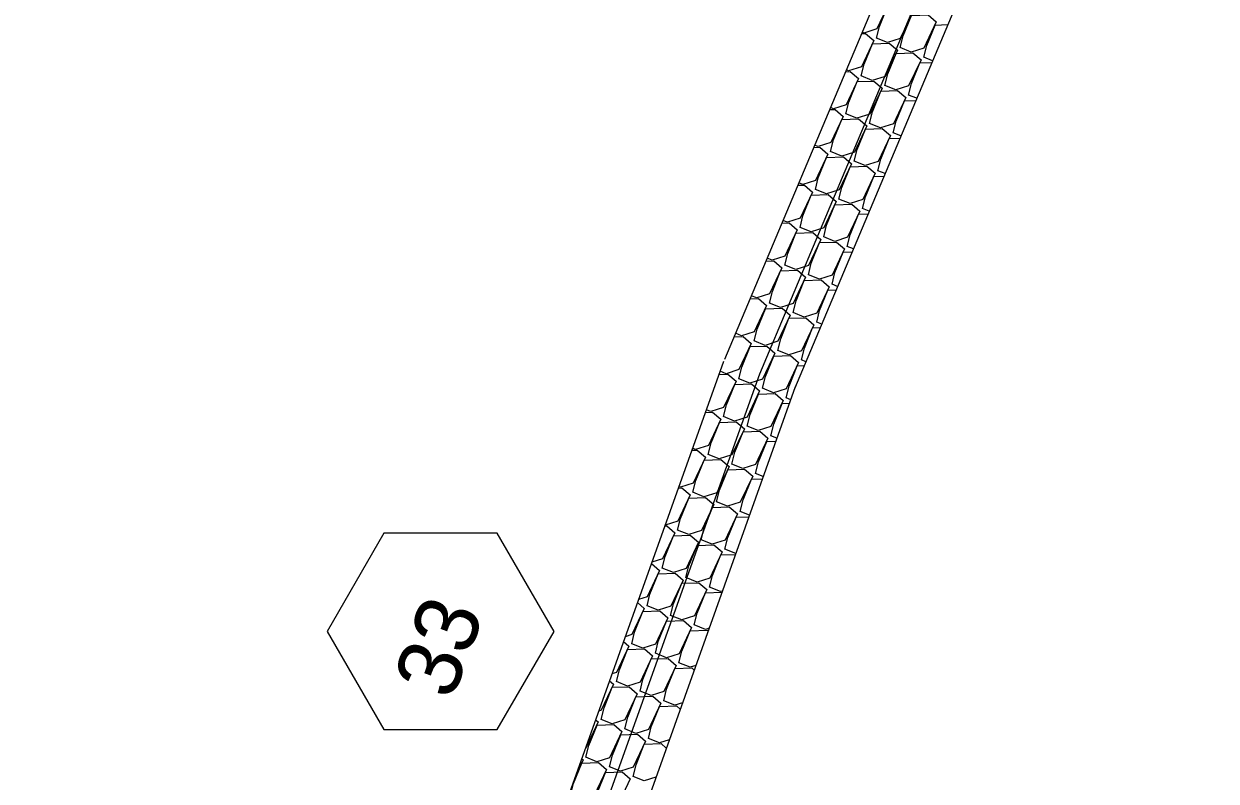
# Model space of a CAD drawing. Extents: x 2384780 to 2405432, y 547869 to 573706.
# Drawn here: x 2395434.7 to 2395528.6, y 556711.6 to 556771.3 of the extents above; entities that cross this region are included whole.
import ezdxf

# ---------------------------------------------------------------- set-up
doc = ezdxf.new("R2010")
doc.units = 0
for name, color, linetype in [('Old_Level_18', 7, 'Continuous'), ('Old_Level_20', 7, 'Continuous'), ('Prop Drainage Box Number Symbol CELL', 7, 'Continuous')]:
    doc.layers.add(name, color=color, linetype=linetype)

msp = doc.modelspace()

# ---------------------------------------------------------------- linework, layer by layer
at = {"layer": 'Old_Level_18'}
for p, q in [((2395525.876, 556822.715), (2395492.638, 556743.689)), ((2395492.638, 556743.689), (2395437.477, 556589.14))]:
    msp.add_line(p, q, dxfattribs=at)
at = {"layer": 'Old_Level_20'}
for p, q in [((2395523.11, 556823.878), (2395489.873, 556744.852)), ((2395528.644, 556821.559), (2395495.404, 556742.526)), ((2395489.813, 556744.697), (2395434.652, 556590.148)), ((2395495.464, 556742.68), (2395440.303, 556588.131))]:
    msp.add_line(p, q, dxfattribs=at)
for points in [[(2395501.933, 556773.519), (2395502.216, 556773.529), (2395502.856, 556772.979), (2395501.882, 556770.914), (2395500.88, 556770.596), (2395500.729, 556770.657)], [(2395501.872, 556770.195), (2395502.103, 556771.115), (2395502.755, 556772.729), (2395504.079, 556772.776), (2395504.72, 556772.226), (2395503.745, 556770.161), (2395502.743, 556769.843), (2395501.872, 556770.195)], [(2395503.735, 556769.442), (2395503.967, 556770.363), (2395504.619, 556771.976), (2395505.943, 556772.023), (2395506.584, 556771.473), (2395505.609, 556769.408), (2395504.607, 556769.09), (2395503.735, 556769.442)], [(2395505.599, 556768.689), (2395505.831, 556769.61), (2395506.482, 556771.223), (2395507.485, 556771.259)], [(2395500.677, 556770.532), (2395501.01, 556770.544), (2395501.65, 556769.993), (2395500.675, 556767.928), (2395499.674, 556767.611), (2395499.481, 556767.688)], [(2395500.666, 556767.209), (2395500.897, 556768.13), (2395501.549, 556769.743), (2395502.873, 556769.791), (2395503.514, 556769.24), (2395502.539, 556767.175), (2395501.537, 556766.858), (2395500.666, 556767.209)], [(2395502.529, 556766.456), (2395502.761, 556767.377), (2395503.413, 556768.99), (2395504.737, 556769.037), (2395505.377, 556768.488), (2395504.403, 556766.422), (2395503.401, 556766.105), (2395502.529, 556766.456)], [(2395506.288, 556768.411), (2395505.599, 556768.689)], [(2395499.421, 556767.544), (2395499.803, 556767.558), (2395500.444, 556767.008), (2395499.469, 556764.943), (2395498.467, 556764.625), (2395498.233, 556764.72)], [(2395504.393, 556765.704), (2395504.624, 556766.624), (2395505.276, 556768.237), (2395506.229, 556768.271)], [(2395499.459, 556764.224), (2395499.691, 556765.144), (2395500.343, 556766.758), (2395501.667, 556766.805), (2395502.308, 556766.255), (2395501.333, 556764.19), (2395500.331, 556763.872), (2395499.459, 556764.224)], [(2395501.323, 556763.471), (2395501.555, 556764.391), (2395502.206, 556766.005), (2395503.53, 556766.052), (2395504.171, 556765.502), (2395503.197, 556763.437), (2395502.195, 556763.119), (2395501.323, 556763.471)], [(2395505.039, 556765.443), (2395504.393, 556765.704)], [(2395503.186, 556762.718), (2395503.418, 556763.639), (2395504.07, 556765.252), (2395504.972, 556765.284)], [(2395498.164, 556764.557), (2395498.597, 556764.573), (2395499.238, 556764.022), (2395498.263, 556761.957), (2395497.261, 556761.639), (2395496.985, 556761.751)], [(2395498.253, 556761.238), (2395498.485, 556762.159), (2395499.137, 556763.772), (2395500.461, 556763.819), (2395501.101, 556763.27), (2395500.127, 556761.204), (2395499.124, 556760.887), (2395498.253, 556761.238)], [(2395500.117, 556760.486), (2395500.348, 556761.406), (2395501, 556763.019), (2395502.324, 556763.066), (2395502.965, 556762.517), (2395501.99, 556760.451), (2395500.988, 556760.133), (2395500.117, 556760.486)], [(2395503.79, 556762.474), (2395503.186, 556762.718)], [(2395501.98, 556759.733), (2395502.212, 556760.653), (2395502.864, 556762.266), (2395503.715, 556762.297)], [(2395496.908, 556761.57), (2395497.391, 556761.587), (2395498.031, 556761.037), (2395497.057, 556758.971), (2395496.055, 556758.654), (2395495.736, 556758.782)], [(2395497.047, 556758.253), (2395497.279, 556759.173), (2395497.93, 556760.787), (2395499.255, 556760.834), (2395499.895, 556760.284), (2395498.92, 556758.219), (2395497.918, 556757.901), (2395497.047, 556758.253)], [(2395498.911, 556757.5), (2395499.142, 556758.42), (2395499.794, 556760.034), (2395501.118, 556760.081), (2395501.759, 556759.531), (2395500.784, 556757.466), (2395499.782, 556757.148), (2395498.911, 556757.5)], [(2395500.774, 556756.747), (2395501.006, 556757.667), (2395501.658, 556759.28), (2395502.459, 556759.309)], [(2395502.541, 556759.506), (2395501.98, 556759.733)], [(2395495.652, 556758.582), (2395496.184, 556758.601), (2395496.825, 556758.051), (2395495.851, 556755.986), (2395494.848, 556755.668), (2395494.488, 556755.814)], [(2395495.84, 556755.267), (2395496.072, 556756.188), (2395496.724, 556757.801), (2395498.048, 556757.848), (2395498.689, 556757.299), (2395497.714, 556755.233), (2395496.712, 556754.915), (2395495.84, 556755.267)], [(2395497.704, 556754.515), (2395497.936, 556755.435), (2395498.588, 556757.048), (2395499.912, 556757.096), (2395500.553, 556756.546), (2395499.578, 556754.48), (2395498.576, 556754.162), (2395497.704, 556754.515)], [(2395499.568, 556753.762), (2395499.8, 556754.682), (2395500.451, 556756.295), (2395501.202, 556756.322)], [(2395501.293, 556756.537), (2395500.774, 556756.747)], [(2395494.396, 556755.595), (2395494.978, 556755.616), (2395495.619, 556755.066), (2395494.644, 556753), (2395493.642, 556752.683), (2395493.239, 556752.846)], [(2395494.634, 556752.282), (2395494.866, 556753.202), (2395495.518, 556754.816), (2395496.842, 556754.863), (2395497.482, 556754.313), (2395496.508, 556752.248), (2395495.506, 556751.93), (2395494.634, 556752.282)], [(2395496.498, 556751.529), (2395496.729, 556752.449), (2395497.382, 556754.062), (2395498.706, 556754.11), (2395499.346, 556753.56), (2395498.371, 556751.495), (2395497.37, 556751.177), (2395496.498, 556751.529)], [(2395498.362, 556750.776), (2395498.593, 556751.696), (2395499.245, 556753.309), (2395499.945, 556753.335)], [(2395500.044, 556753.569), (2395499.568, 556753.762)], [(2395493.139, 556752.608), (2395493.772, 556752.63), (2395494.413, 556752.08), (2395493.438, 556750.015), (2395492.436, 556749.697), (2395491.991, 556749.877)], [(2395493.428, 556749.296), (2395493.66, 556750.216), (2395494.311, 556751.83), (2395495.636, 556751.877), (2395496.276, 556751.327), (2395495.302, 556749.262), (2395494.3, 556748.944), (2395493.428, 556749.296)], [(2395495.292, 556748.544), (2395495.523, 556749.464), (2395496.175, 556751.077), (2395497.499, 556751.125), (2395498.14, 556750.574), (2395497.165, 556748.509), (2395496.163, 556748.191), (2395495.292, 556748.544)], [(2395498.796, 556750.601), (2395498.362, 556750.776)], [(2395491.883, 556749.62), (2395492.566, 556749.645), (2395493.206, 556749.095), (2395492.232, 556747.03), (2395491.23, 556746.712), (2395490.743, 556746.909)], [(2395497.155, 556747.791), (2395497.387, 556748.711), (2395498.039, 556750.324), (2395498.689, 556750.347)], [(2395492.222, 556746.311), (2395492.453, 556747.231), (2395493.105, 556748.845), (2395494.43, 556748.892), (2395495.07, 556748.342), (2395494.095, 556746.277), (2395493.093, 556745.959), (2395492.222, 556746.311)], [(2395494.086, 556745.558), (2395494.317, 556746.478), (2395494.969, 556748.091), (2395496.293, 556748.139), (2395496.934, 556747.589), (2395495.959, 556745.524), (2395494.957, 556745.206), (2395494.086, 556745.558)], [(2395497.547, 556747.632), (2395497.155, 556747.791)], [(2395495.949, 556744.805), (2395496.181, 556745.725), (2395496.833, 556747.338), (2395497.432, 556747.36)], [(2395490.627, 556746.633), (2395491.36, 556746.659), (2395492, 556746.109), (2395491.025, 556744.044), (2395490.024, 556743.726), (2395489.536, 556743.923)], [(2395491.016, 556743.325), (2395491.247, 556744.245), (2395491.899, 556745.859), (2395493.223, 556745.906), (2395493.864, 556745.356), (2395492.889, 556743.291), (2395491.887, 556742.973), (2395491.016, 556743.325)], [(2395492.879, 556742.572), (2395493.111, 556743.493), (2395493.763, 556745.106), (2395495.087, 556745.153), (2395495.728, 556744.603), (2395494.753, 556742.538), (2395493.751, 556742.22), (2395492.879, 556742.572)], [(2395494.743, 556741.819), (2395494.975, 556742.74), (2395495.626, 556744.353), (2395496.176, 556744.373)], [(2395496.298, 556744.664), (2395495.949, 556744.805)], [(2395489.439, 556743.648), (2395490.154, 556743.674), (2395490.794, 556743.124), (2395489.819, 556741.059), (2395488.817, 556740.74), (2395488.453, 556740.887)], [(2395489.809, 556740.34), (2395490.041, 556741.26), (2395490.693, 556742.873), (2395492.017, 556742.921), (2395492.658, 556742.371), (2395491.683, 556740.306), (2395490.681, 556739.988), (2395489.809, 556740.34)], [(2395491.673, 556739.587), (2395491.905, 556740.507), (2395492.556, 556742.12), (2395493.881, 556742.168), (2395494.521, 556741.618), (2395493.547, 556739.552), (2395492.545, 556739.235), (2395491.673, 556739.587)], [(2395493.537, 556738.834), (2395493.768, 556739.754), (2395494.42, 556741.368), (2395495.003, 556741.388)], [(2395495.104, 556741.674), (2395494.743, 556741.819)], [(2395488.375, 556740.668), (2395488.947, 556740.688), (2395489.588, 556740.138), (2395488.613, 556738.073), (2395487.611, 556737.755), (2395487.371, 556737.852)], [(2395488.603, 556737.354), (2395488.835, 556738.275), (2395489.487, 556739.888), (2395490.811, 556739.935), (2395491.451, 556739.385), (2395490.477, 556737.32), (2395489.475, 556737.002), (2395488.603, 556737.354)], [(2395490.467, 556736.601), (2395490.698, 556737.522), (2395491.35, 556739.135), (2395492.675, 556739.182), (2395493.315, 556738.632), (2395492.34, 556736.567), (2395491.339, 556736.249), (2395490.467, 556736.601)], [(2395492.331, 556735.848), (2395492.562, 556736.769), (2395493.214, 556738.382), (2395493.939, 556738.408)], [(2395494.021, 556738.638), (2395493.537, 556738.834)], [(2395487.311, 556737.687), (2395487.741, 556737.703), (2395488.382, 556737.152), (2395487.407, 556735.087), (2395486.405, 556734.77), (2395486.288, 556734.817)], [(2395487.397, 556734.369), (2395487.629, 556735.289), (2395488.28, 556736.902), (2395489.604, 556736.95), (2395490.245, 556736.4), (2395489.271, 556734.334), (2395488.269, 556734.017), (2395487.397, 556734.369)], [(2395489.26, 556733.616), (2395489.492, 556734.536), (2395490.144, 556736.149), (2395491.468, 556736.197), (2395492.109, 556735.647), (2395491.134, 556733.581), (2395490.132, 556733.264), (2395489.26, 556733.616)], [(2395492.938, 556735.603), (2395492.331, 556735.848)], [(2395486.248, 556734.707), (2395486.535, 556734.717), (2395487.175, 556734.167), (2395486.201, 556732.102), (2395485.206, 556731.786)], [(2395491.124, 556732.863), (2395491.356, 556733.783), (2395492.008, 556735.396), (2395492.875, 556735.427)], [(2395486.191, 556731.383), (2395486.422, 556732.304), (2395487.074, 556733.917), (2395488.398, 556733.964), (2395489.039, 556733.414), (2395488.064, 556731.349), (2395487.062, 556731.031), (2395486.191, 556731.383)], [(2395488.055, 556730.63), (2395488.286, 556731.551), (2395488.938, 556733.164), (2395490.262, 556733.211), (2395490.902, 556732.661), (2395489.928, 556730.596), (2395488.926, 556730.278), (2395488.055, 556730.63)], [(2395491.854, 556732.568), (2395491.124, 556732.863)], [(2395485.185, 556731.726), (2395485.328, 556731.731), (2395485.969, 556731.182), (2395484.995, 556729.116), (2395484.159, 556728.851)], [(2395489.918, 556729.877), (2395490.15, 556730.797), (2395490.802, 556732.411), (2395491.811, 556732.447)], [(2395484.985, 556728.398), (2395485.216, 556729.318), (2395485.868, 556730.931), (2395487.192, 556730.978), (2395487.833, 556730.429), (2395486.858, 556728.363), (2395485.856, 556728.046), (2395484.985, 556728.398)], [(2395486.848, 556727.645), (2395487.08, 556728.565), (2395487.732, 556730.178), (2395489.056, 556730.226), (2395489.696, 556729.676), (2395488.722, 556727.61), (2395487.72, 556727.292), (2395486.848, 556727.645)], [(2395490.771, 556729.533), (2395489.918, 556729.877)], [(2395488.712, 556726.892), (2395488.944, 556727.812), (2395489.595, 556729.425), (2395490.748, 556729.466)], [(2395484.121, 556728.746), (2395484.122, 556728.746), (2395484.763, 556728.196), (2395483.788, 556726.131), (2395483.112, 556725.916)], [(2395483.778, 556725.412), (2395484.01, 556726.332), (2395484.662, 556727.946), (2395485.986, 556727.993), (2395486.627, 556727.443), (2395485.652, 556725.378), (2395484.65, 556725.06), (2395483.778, 556725.412)], [(2395485.642, 556724.659), (2395485.874, 556725.579), (2395486.525, 556727.193), (2395487.85, 556727.24), (2395488.49, 556726.69), (2395487.516, 556724.625), (2395486.513, 556724.307), (2395485.642, 556724.659)], [(2395487.505, 556723.906), (2395487.737, 556724.826), (2395488.389, 556726.44), (2395489.684, 556726.486)], [(2395489.718, 556726.582), (2395489.583, 556726.539), (2395488.712, 556726.892)], [(2395483.023, 556725.669), (2395483.556, 556725.211), (2395482.582, 556723.145), (2395482.064, 556722.981)], [(2395482.572, 556722.427), (2395482.804, 556723.347), (2395483.456, 556724.96), (2395484.78, 556725.008), (2395485.42, 556724.458), (2395484.445, 556722.392), (2395483.444, 556722.074), (2395482.572, 556722.427)], [(2395484.436, 556721.674), (2395484.667, 556722.594), (2395485.319, 556724.207), (2395486.643, 556724.255), (2395487.284, 556723.704), (2395486.309, 556721.639), (2395485.307, 556721.321), (2395484.436, 556721.674)], [(2395486.299, 556720.921), (2395486.531, 556721.841), (2395487.183, 556723.454), (2395488.507, 556723.502), (2395488.593, 556723.428)], [(2395488.671, 556723.647), (2395488.377, 556723.554), (2395487.505, 556723.906)], [(2395481.925, 556722.59), (2395482.351, 556722.225), (2395481.376, 556720.16), (2395481.017, 556720.046)], [(2395481.366, 556719.441), (2395481.598, 556720.361), (2395482.249, 556721.975), (2395483.573, 556722.022), (2395484.214, 556721.472), (2395483.24, 556719.407), (2395482.238, 556719.089), (2395481.366, 556719.441)], [(2395483.229, 556718.688), (2395483.461, 556719.608), (2395484.113, 556721.222), (2395485.437, 556721.269), (2395486.078, 556720.719), (2395485.103, 556718.654), (2395484.101, 556718.336), (2395483.229, 556718.688)], [(2395485.093, 556717.935), (2395485.325, 556718.855), (2395485.976, 556720.469), (2395487.301, 556720.516), (2395487.494, 556720.35)], [(2395487.623, 556720.712), (2395487.171, 556720.569), (2395486.299, 556720.921)], [(2395480.827, 556719.512), (2395481.144, 556719.24), (2395480.169, 556717.174), (2395479.97, 556717.111)], [(2395480.16, 556716.456), (2395480.391, 556717.376), (2395481.043, 556718.989), (2395482.367, 556719.037), (2395483.008, 556718.486), (2395482.033, 556716.421), (2395481.031, 556716.103), (2395480.16, 556716.456)], [(2395482.023, 556715.703), (2395482.255, 556716.623), (2395482.907, 556718.236), (2395484.231, 556718.284), (2395484.871, 556717.733), (2395483.897, 556715.668), (2395482.895, 556715.351), (2395482.023, 556715.703)], [(2395486.575, 556717.777), (2395485.965, 556717.583), (2395485.093, 556717.935)], [(2395483.887, 556714.949), (2395484.118, 556715.87), (2395484.77, 556717.483), (2395486.095, 556717.53), (2395486.395, 556717.272)], [(2395479.728, 556716.434), (2395479.938, 556716.254), (2395478.963, 556714.189), (2395478.922, 556714.176)], [(2395478.953, 556713.47), (2395479.185, 556714.39), (2395479.837, 556716.003), (2395481.161, 556716.051), (2395481.802, 556715.501), (2395480.827, 556713.436), (2395479.825, 556713.118), (2395478.953, 556713.47)], [(2395480.817, 556712.717), (2395481.049, 556713.637), (2395481.701, 556715.25), (2395483.024, 556715.298), (2395483.665, 556714.748), (2395482.691, 556712.683), (2395481.689, 556712.365), (2395480.817, 556712.717)], [(2395485.528, 556714.841), (2395484.758, 556714.598), (2395483.887, 556714.949)], [(2395482.681, 556711.964), (2395482.912, 556712.884), (2395483.564, 556714.498), (2395484.888, 556714.545), (2395485.297, 556714.194)], [(2395477.747, 556710.485), (2395477.979, 556711.405), (2395478.63, 556713.018), (2395479.955, 556713.066), (2395480.595, 556712.515), (2395479.621, 556710.45), (2395478.619, 556710.132), (2395477.747, 556710.485)], [(2395478.63, 556713.356), (2395478.732, 556713.268), (2395478.187, 556712.114)], [(2395479.611, 556709.731), (2395479.843, 556710.652), (2395480.494, 556712.265), (2395481.819, 556712.312), (2395482.459, 556711.762), (2395481.484, 556709.697), (2395480.482, 556709.379), (2395479.611, 556709.731)], [(2395484.48, 556711.906), (2395483.552, 556711.612), (2395482.681, 556711.964)]]:
    msp.add_lwpolyline(points, dxfattribs=at)
at = {"layer": 'Prop Drainage Box Number Symbol CELL'}
msp.add_lwpolyline([(2395476.449, 556723.401), (2395471.974, 556731.151), (2395463.025, 556731.151), (2395458.551, 556723.401), (2395463.025, 556715.651), (2395471.974, 556715.651)], close=True, dxfattribs=at)

# ---------------------------------------------------------------- texts
msp.add_text('33', height=5, rotation=69.76581, dxfattribs=at).set_placement((2395468.392, 556717.855))

doc.saveas('drawing.dxf')
